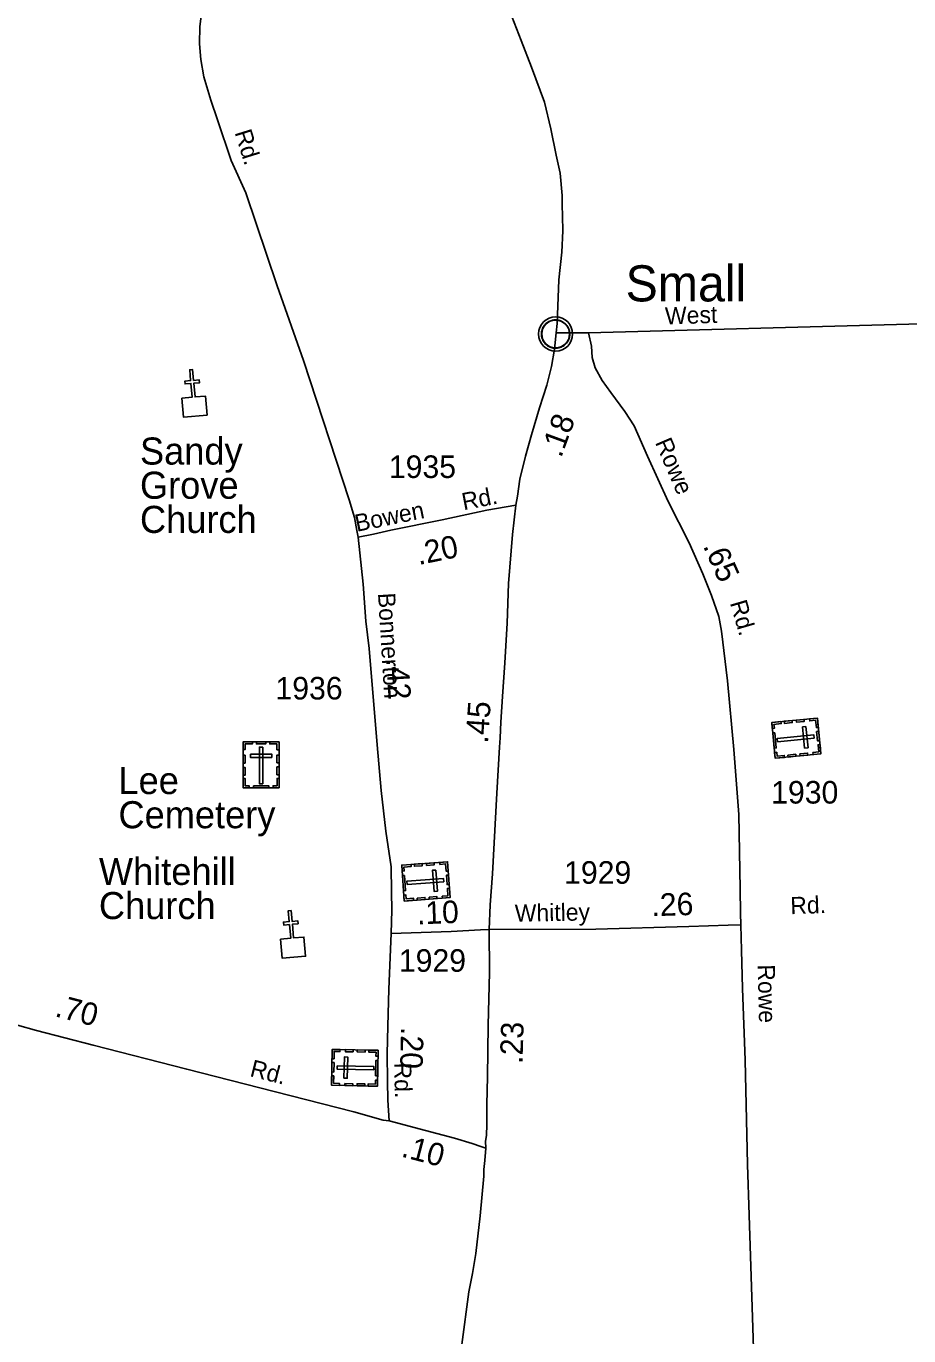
# Model space of a CAD drawing. Extents: x 2532689 to 2764727, y 536648 to 732970.
# Drawn here: x 2637560 to 2642450, y 558115 to 565369 of the extents above; entities that cross this region are included whole.
import ezdxf

# ---------------------------------------------------------------- set-up
doc = ezdxf.new("R2010")
doc.units = 0
for name, color, linetype in [('Exist Civil Demographics Community CELL', 7, 'Continuous'), ('Exist Civil Demographics Community Label', 7, 'Continuous'), ('Exist Cultural Cemetery CELL', 7, 'Continuous'), ('Exist Cultural Cemetery Label', 7, 'Continuous'), ('Exist Cultural Church CELL', 7, 'Continuous'), ('Exist Cultural Church Label', 7, 'Continuous'), ('Exist Road Primary Interstate Shield CELL', 7, 'Continuous'), ('Exist Road Primary NC Attributed', 7, 'Continuous'), ('Exist Road Primary NC Mileage Hundredths English Label', 7, 'Continuous'), ('Exist Road Secondary Mileage Hundredths English Label', 7, 'Continuous'), ('Exist Road Secondary Type 20 Attributed', 7, 'Continuous'), ('Exist Road Secondary Type 51 Attributed', 7, 'Continuous'), ('Exist Road Secondary Type 51 Label', 7, 'Continuous'), ('Exist Road Secondary Type 51 Number Label', 7, 'Continuous')]:
    doc.layers.add(name, color=color, linetype=linetype)

# ---------------------------------------------------------------- blocks, each defined once
blk = doc.blocks.new('Exist Cultural Church')
at = {"layer": 'Exist Road Primary Interstate Shield CELL'}
blk.add_lwpolyline([(-65.2, 26.9), (-8.3, 27), (-8.3, 103.2), (-40.3, 103.2), (-40.3, 119.2), (-8.3, 119.2), (-8.3, 179.3), (7.7, 179.3), (7.7, 119.2), (39.7, 119.2), (39.7, 103.2), (7.7, 103.2), (7.7, 27), (65.4, 26.9), (65.4, -79.5), (-65.2, -79.5)], close=True, dxfattribs=at)
blk = doc.blocks.new('Exist Cultural Cemetery')
at = {"layer": 'Exist Cultural Cemetery CELL'}
for points in [[(-99.7, 130.7), (99.4, 130.7), (99.4, -123.9), (-99.7, -123.9)], [(-99.7, 87.4), (-88.3, 87.4), (-88.3, 119.6), (-47.8, 119.6), (-47.8, 130.7), (-99.7, 130.7)], [(-25.6, 130.7), (26.2, 130.7), (26.2, 119.3), (-25.6, 119.3)], [(9.3, 101.4), (-9.3, 101.4), (-9.3, -101.4), (9.3, -101.4)], [(99.5, 87.3), (88.1, 87.3), (88.1, 119.5), (47.6, 119.5), (47.6, 130.6), (99.5, 130.6)], [(-99.7, 13.2), (-99.7, 56.5), (-88.3, 56.5), (-88.3, 13.2)], [(-58.9, 62.6), (-58.9, 44), (58.9, 44), (58.9, 62.6)], [(88.1, 14.3), (88.1, 57.6), (99.4, 57.6), (99.4, 14.3)], [(-99.7, -54), (-99.7, -10.7), (-88.3, -10.7), (-88.3, -54)], [(-66.6, -123.9), (-66.6, -112.4), (-88.6, -112.4), (-88.6, -72), (-99.7, -72), (-99.7, -123.9)], [(66.3, -123.9), (66.3, -112.4), (88.3, -112.4), (88.3, -72), (99.4, -72), (99.4, -123.9)], [(88, -51.7), (88, -8.4), (99.4, -8.4), (99.4, -51.7)], [(-42.2, -112.5), (42.6, -112.5), (42.6, -123.9), (-42.2, -123.9)]]:
    blk.add_lwpolyline(points, close=True, dxfattribs=at)

msp = doc.modelspace()

# ---------------------------------------------------------------- linework, layer by layer
at = {"layer": 'Exist Civil Demographics Community CELL'}
msp.add_lwpolyline([(2640415.2, 563676.6), (2640416.2, 563682.2), (2640418, 563688.8), (2640420.9, 563696), (2640423.9, 563701.7), (2640427.2, 563707.4), (2640430.9, 563712.6), (2640434.9, 563716.9), (2640439.5, 563721.5), (2640445, 563726.1), (2640450.5, 563729.8), (2640455.3, 563732.6), (2640460.4, 563735.1), (2640465.9, 563737.4), (2640471.5, 563739.2), (2640475.8, 563740.4), (2640480.7, 563741.1), (2640484.8, 563741.8), (2640491.2, 563742.1), (2640495.6, 563742), (2640501.3, 563741.7), (2640506.2, 563741), (2640511.1, 563740), (2640516.1, 563738.6), (2640521.2, 563736.7), (2640527.9, 563733.7), (2640534.2, 563730.2), (2640539.2, 563726.7), (2640544.4, 563722.7), (2640547.7, 563719.5), (2640551.8, 563715.2), (2640555.7, 563710.5), (2640558.8, 563705.9), (2640561.9, 563700.9), (2640564.3, 563695.7), (2640566.4, 563690.7), (2640567.9, 563685.7), (2640569.2, 563681.1), (2640570.3, 563675), (2640570.9, 563670.3), (2640571.2, 563664.3), (2640571, 563658.6), (2640570.4, 563652.9), (2640569.5, 563647.4), (2640567.9, 563641.2), (2640566, 563635.4), (2640563.7, 563630.3), (2640560.5, 563624.3), (2640557.2, 563619), (2640553.8, 563614.3), (2640549.6, 563609.6), (2640544.3, 563604.6), (2640539.3, 563600.5), (2640534.3, 563597), (2640529.9, 563594.5), (2640523.1, 563591.3), (2640516, 563588.6), (2640510, 563587.1), (2640503.4, 563585.8), (2640499, 563585.3), (2640494.5, 563585.1), (2640488.9, 563585.1), (2640484.6, 563585.5), (2640479, 563586.2), (2640473.1, 563587.5), (2640468.5, 563588.8), (2640463.3, 563590.7), (2640458.7, 563592.7), (2640454.8, 563594.9), (2640448, 563599), (2640442.4, 563603.3), (2640437.5, 563607.8), (2640433.1, 563612.6), (2640429.9, 563616.6), (2640426.9, 563620.8), (2640422.8, 563627.9), (2640421.1, 563631.4), (2640419.4, 563635.4), (2640416.8, 563643.6), (2640415.2, 563650.7), (2640414.6, 563655.8), (2640414.2, 563662.2), (2640414.2, 563666.8), (2640414.7, 563673.3)], close=True, dxfattribs=at)
for centre, radius in [((2640492.9, 563664.2), 94.3), ((2640492.6, 563664.5), 76.7)]:
    msp.add_circle(centre, radius, dxfattribs=at)
at = {"layer": 'Exist Cultural Cemetery CELL'}
for points in [[(2641943.2, 561536.8), (2641962.8, 561338.7), (2641709.4, 561313.7), (2641689.8, 561511.8)], [(2641693.1, 561478.9), (2641704.6, 561480), (2641702.4, 561501.9), (2641742.6, 561505.9), (2641741.5, 561517), (2641689.9, 561511.9)], [(2641759.4, 561518.7), (2641802.5, 561523), (2641803.7, 561511.6), (2641760.6, 561507.4)], [(2641826.3, 561525.3), (2641869.4, 561529.6), (2641870.6, 561518.2), (2641827.4, 561514)], [(2641900.1, 561532.6), (2641901.2, 561521.3), (2641933.3, 561524.4), (2641937.3, 561484.1), (2641948.3, 561485.2), (2641943.2, 561536.8)], [(2641706.9, 561455.8), (2641715.2, 561371.3), (2641703.9, 561370.2), (2641695.6, 561454.6)], [(2641924.8, 561425.5), (2641922.9, 561444), (2641721.1, 561424.1), (2641723, 561405.5)], [(2641879.5, 561489.5), (2641860.9, 561487.7), (2641872.5, 561370.5), (2641891.1, 561372.4)], [(2641950.5, 561463.1), (2641955.6, 561411.5), (2641944.2, 561410.4), (2641939.1, 561462)], [(2641706.1, 561346.7), (2641717.6, 561347.8), (2641719.7, 561325.9), (2641759.9, 561329.9), (2641761, 561318.8), (2641709.4, 561313.7)], [(2641919.6, 561334.4), (2641918.5, 561345.7), (2641950.6, 561348.8), (2641946.6, 561389.2), (2641957.7, 561390.3), (2641962.7, 561338.6)], [(2641780.2, 561332.1), (2641823.3, 561336.4), (2641824.4, 561325), (2641781.3, 561320.8)], [(2641845.8, 561338.6), (2641888.9, 561342.8), (2641890, 561331.5), (2641846.9, 561327.2)], [(2639893.9, 560740.5), (2639908.5, 560542), (2639654.6, 560523.3), (2639639.9, 560721.8)], [(2639642.4, 560688.9), (2639653.9, 560689.7), (2639652.2, 560711.6), (2639692.5, 560714.6), (2639691.7, 560725.7), (2639640, 560721.9)], [(2639709.7, 560727), (2639752.9, 560730.2), (2639753.7, 560718.8), (2639710.5, 560715.7)], [(2639776.7, 560731.9), (2639819.9, 560735.1), (2639820.7, 560723.8), (2639777.5, 560720.6)], [(2639829, 560694.8), (2639810.4, 560693.5), (2639819, 560576.1), (2639837.6, 560577.4)], [(2639850.7, 560737.4), (2639851.5, 560726.1), (2639883.6, 560728.4), (2639886.6, 560688), (2639897.7, 560688.8), (2639893.9, 560740.5)], [(2639655.6, 560665.4), (2639661.8, 560580.7), (2639650.5, 560579.9), (2639644.2, 560664.5)], [(2639872.7, 560629.7), (2639871.3, 560648.3), (2639669, 560633.4), (2639670.4, 560614.8)], [(2639899.3, 560666.7), (2639903.1, 560615), (2639891.7, 560614.2), (2639887.9, 560665.8)], [(2639652.1, 560556.3), (2639663.6, 560557.2), (2639665.2, 560535.2), (2639705.5, 560538.2), (2639706.3, 560527.1), (2639654.6, 560523.3)], [(2639865.3, 560538.7), (2639864.4, 560550.1), (2639896.5, 560552.4), (2639893.5, 560592.9), (2639904.6, 560593.7), (2639908.5, 560541.9)], [(2639725.8, 560539.9), (2639769, 560543.1), (2639769.8, 560531.8), (2639726.6, 560528.6)], [(2639791.5, 560544.8), (2639834.7, 560547.9), (2639835.6, 560536.6), (2639792.4, 560533.4)], [(2639251.3, 559502.3), (2639254.9, 559701.3), (2639509.5, 559696.7), (2639505.9, 559497.7)], [(2639298.2, 559700.6), (2639298, 559689.3), (2639265.8, 559689.8), (2639265.1, 559649.3), (2639254, 559649.5), (2639254.9, 559701.4)], [(2639371.1, 559687.9), (2639327.8, 559688.7), (2639328, 559700), (2639371.3, 559699.3)], [(2639437, 559686.7), (2639393.7, 559687.4), (2639393.9, 559698.8), (2639437.2, 559698)], [(2639508.9, 559663.6), (2639497.4, 559663.8), (2639497.8, 559685.8), (2639457.4, 559686.5), (2639457.6, 559697.7), (2639509.5, 559696.7)], [(2639252.6, 559576.3), (2639253.6, 559628.1), (2639265, 559627.9), (2639264, 559576.1)], [(2639282.6, 559610.7), (2639282.2, 559592.1), (2639485, 559588.4), (2639485.3, 559607.1)], [(2639320.1, 559541.8), (2639338.7, 559541.5), (2639340.9, 559659.2), (2639322.2, 559659.6)], [(2639495.4, 559555.3), (2639497, 559640.2), (2639508.4, 559640), (2639506.8, 559555.1)], [(2639294.6, 559501.5), (2639294.8, 559512.8), (2639262.6, 559513.4), (2639263.4, 559554), (2639252.2, 559554.2), (2639251.3, 559502.3)], [(2639368.7, 559500.1), (2639325.4, 559500.9), (2639325.6, 559512.3), (2639369, 559511.5)], [(2639436, 559498.9), (2639392.6, 559499.7), (2639392.9, 559511.1), (2639436.2, 559510.3)], [(2639506.4, 559530.7), (2639494.9, 559531), (2639494.5, 559509), (2639454.1, 559509.7), (2639453.9, 559498.6), (2639505.8, 559497.6)]]:
    msp.add_lwpolyline(points, close=True, dxfattribs=at)
at = {"layer": 'Exist Road Primary NC Attributed'}
for points in [[(2640495.2, 563670.4), (2640500.9, 563722.3), (2640511.5, 563963.6), (2640527.7, 564118.2), (2640533.1, 564235.6), (2640531.3, 564317.4), (2640528.6, 564380.5), (2640528.9, 564431.8), (2640518.9, 564554.7), (2640496.4, 564655), (2640465.5, 564800.1), (2640431.7, 564948.6), (2640358.8, 565141.4), (2640301.1, 565289.2), (2640210.8, 565525.4)], [(2640272.1, 562716.1), (2640281.5, 562765.4), (2640294.4, 562860.5), (2640326.6, 562987.7), (2640359, 563105.6), (2640403.1, 563254.3), (2640443.8, 563380.7), (2640469.2, 563485), (2640487.5, 563581.1), (2640495.2, 563670.4)], [(2640124.1, 560364.6), (2640130.6, 560501.6), (2640143.5, 560674), (2640152.1, 560846.5), (2640167.7, 561120.3), (2640182.2, 561374.9), (2640185.4, 561428.1), (2640188.6, 561513.5), (2640198.4, 561656.6), (2640210.6, 561843), (2640224.4, 562061.7), (2640231.5, 562282), (2640254.1, 562554.3), (2640272.1, 562716.1)], [(2640105.5, 559153.5), (2640105.2, 559192.9), (2640109.4, 559225.1), (2640112.4, 559285.6), (2640112.4, 559396.2), (2640115.9, 559549.6), (2640119.5, 559835), (2640126.6, 560127.6), (2640124.1, 560364.6)], [(2639852.7, 556083.6), (2639845.8, 556161.8), (2639836.1, 556243.3), (2639824.5, 556320.9), (2639814.4, 556435.8), (2639810.9, 556545.9), (2639814.8, 556629.3), (2639822.9, 556807.3), (2639852.8, 557012.2), (2639891.3, 557349.6), (2639897, 557427.9), (2639918.3, 557590.2), (2639953.1, 557787.8), (2639973, 558066.4), (2640011.8, 558359), (2640032.7, 558459.9), (2640050.1, 558571.2), (2640073.9, 558779.9), (2640095.5, 558998.4), (2640096, 559036.7), (2640100.7, 559086.8), (2640105.5, 559153.5)]]:
    msp.add_lwpolyline(points, dxfattribs=at)
at = {"layer": 'Exist Road Secondary Type 20 Attributed'}
for points in [[(2648489.7, 563891.5), (2647357.2, 563850.6), (2644224.6, 563767.4), (2640674.4, 563670.9)], [(2640674.4, 563670.9), (2640495.2, 563670.4)], [(2640674.4, 563670.9), (2640691.2, 563596.4), (2640696, 563534.9), (2640712.4, 563477.3), (2640750.3, 563405.7), (2640798.4, 563340.3), (2640876.2, 563234.6), (2640927.2, 563155.8), (2641001.2, 562986.7), (2641115.5, 562736.8), (2641231.8, 562507.1), (2641308.7, 562335.1), (2641355.8, 562215.9), (2641396.2, 562099.6), (2641412.5, 562017.9), (2641445.2, 561742.1), (2641479.8, 561363.5), (2641507.6, 561002.1), (2641515.8, 560590.3), (2641516.8, 560455.8), (2641518.7, 560391.4)], [(2640272.1, 562716.1), (2640112.2, 562688.1), (2639863.9, 562634.9), (2639580.2, 562576.9), (2639483.5, 562554.9), (2639398.5, 562538.3)], [(2641518.7, 560391.4), (2641448.5, 560389.4), (2641230.4, 560382.6), (2640714.9, 560367.3), (2640124.1, 560364.6)], [(2641518.7, 560391.4), (2641523, 560251.5), (2641527.8, 560038.2), (2641543.2, 559642.2), (2641556.2, 559063.2), (2641565.8, 558782.6), (2641583.1, 558216.5), (2641593.6, 557929.2), (2641609, 557389.1), (2641615.3, 556827.4), (2641607.6, 556620.7), (2641602.8, 556455.4), (2641624.4, 556285.8), (2641642.7, 556184.9), (2641656.1, 556092.6), (2641661.9, 556036.9)]]:
    msp.add_lwpolyline(points, dxfattribs=at)
at = {"layer": 'Exist Road Secondary Type 51 Attributed'}
for points in [[(2639398.5, 562538.3), (2639391.9, 562576.2), (2639378, 562648.2), (2639349.7, 562745.5), (2639095.7, 563516.7), (2638950.6, 563931.5), (2638776.2, 564447), (2638694.3, 564625.4), (2638619.3, 564850.5), (2638581.8, 564959.6), (2638544.2, 565089.2), (2638527.2, 565184.7), (2638520.4, 565271.7), (2638522.1, 565367.2), (2638540.8, 565512.2)], [(2639582.5, 560343.7), (2639585.7, 560472.6), (2639584.2, 560574.1), (2639581.3, 560711.9), (2639551.4, 560911.1), (2639526.6, 561135.8), (2639503.6, 561388.7), (2639459.4, 561922.9), (2639441.7, 562073.3), (2639425.8, 562278.5), (2639398.5, 562538.3)], [(2639569.8, 559305.9), (2639537.8, 559309.2), (2639374.7, 559355.5), (2638934.2, 559467.7), (2638449.5, 559591), (2637930.2, 559725.6), (2637616.7, 559806.5), (2637511.7, 559836.4), (2637434.8, 559886.8), (2637320.9, 559968.3), (2637131.9, 560093.9), (2637040.6, 560159.9), (2636961.7, 560194.4), (2636861, 560224.2), (2636579.1, 560310), (2636092.1, 560451.2)], [(2639569.8, 559305.9), (2639563.6, 559419.6), (2639561.2, 559525.5), (2639559.7, 559677.5), (2639562.4, 559829.6), (2639569.6, 560034.3), (2639582.5, 560343.7)], [(2640124.1, 560364.6), (2640077.4, 560363), (2639914.6, 560355), (2639582.5, 560343.7)], [(2640105.5, 559153.5), (2640077.8, 559163.7), (2640030.9, 559180), (2639932.2, 559209.9), (2639771.2, 559252.3), (2639569.8, 559305.9)]]:
    msp.add_lwpolyline(points, dxfattribs=at)

# ---------------------------------------------------------------- block references
at = {"layer": 'Exist Cultural Cemetery CELL'}
msp.add_blockref('Exist Cultural Cemetery', (2638861, 561274.3), dxfattribs=at)
at = {"layer": 'Exist Cultural Church CELL', "rotation": 5.063636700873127}
for p in [(2638489.6, 563288), (2639035.7, 560291.1)]:
    msp.add_blockref('Exist Cultural Church', p, dxfattribs=at)

# ---------------------------------------------------------------- texts
at = {"layer": 'Exist Civil Demographics Community Label'}
msp.add_text('Small', height=200, dxfattribs=at).set_placement((2640880.5, 563844.7))
at = {"layer": 'Exist Cultural Cemetery Label'}
for s, p in [('Lee', (2638070.8, 561115.7)), ('Cemetery', (2638070.8, 560926.3))]:
    msp.add_text(s, height=150, dxfattribs=at).set_placement(p)
at = {"layer": 'Exist Cultural Church Label'}
for s, p in [('Sandy', (2638190, 562940.9)), ('Grove', (2638190, 562751.6)), ('Church', (2638190, 562562.2)), ('Whitehill', (2637962.5, 560612.3)), ('Church', (2637962.5, 560423))]:
    msp.add_text(s, height=150, dxfattribs=at).set_placement(p)
at = {"layer": 'Exist Road Primary NC Mileage Hundredths English Label'}
for s, rotation, p in [('.18', 69.93016, (2640523.2, 562974.4)), ('.45', 86.07353, (2640117.8, 561393.9)), ('.23', 88.18431, (2640309, 559620.1))]:
    msp.add_text(s, height=125, rotation=rotation, dxfattribs=at).set_placement(p)
at = {"layer": 'Exist Road Secondary Mileage Hundredths English Label'}
for s, rotation, p in [('.20', 11.52493, (2639733.9, 562383.8)), ('.65', 294.08118, (2641307.8, 562490.3)), ('.42', 273.46244, (2639553.5, 561866.7)), ('.26', 1.69283, (2641025.4, 560439)), ('.10', 2.10081, (2639726.2, 560393.7)), ('.70', 345.53025, (2637713.6, 559885.4)), ('.20', 268.64125, (2639636.6, 559826.5)), ('.10', 345.23517, (2639632.6, 559108.7))]:
    msp.add_text(s, height=125, rotation=rotation, dxfattribs=at).set_placement(p)
at = {"layer": 'Exist Road Secondary Type 51 Label'}
for s, rotation, p in [('Rd.', 287.29508, (2638713.5, 564780.8)), ('West', 1.84619, (2641100.5, 563716.6)), ('Rowe', 293.19748, (2641042.3, 563063.7)), ('Rd.', 11.05351, (2639983.1, 562687.6)), ('Bowen', 11.52475, (2639391.1, 562568.1)), ('Bonnerton', 273.46244, (2639508.5, 562228.1)), ('Rd.', 286.28842, (2641457.7, 562175)), ('Rd.', 2.11799, (2641794.9, 560449.9)), ('Whitley', 1.07092, (2640267.6, 560408.2)), ('Rowe', 271.24281, (2641612.6, 560171.2)), ('Rd.', 345.73193, (2638794.2, 559554.1)), ('Rd.', 271.24521, (2639598.4, 559627.5))]:
    msp.add_text(s, height=95, rotation=rotation, dxfattribs=at).set_placement(p)
at = {"layer": 'Exist Road Secondary Type 51 Number Label'}
for s, p in [('1935', (2639569.1, 562866.6)), ('1936', (2638940.7, 561639.6)), ('1930', (2641687.2, 561063.1)), ('1929', (2640540, 560619)), ('1929', (2639624.5, 560131.3))]:
    msp.add_text(s, height=125, dxfattribs=at).set_placement(p)

doc.saveas('drawing.dxf')
